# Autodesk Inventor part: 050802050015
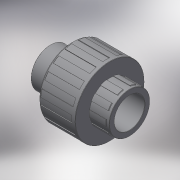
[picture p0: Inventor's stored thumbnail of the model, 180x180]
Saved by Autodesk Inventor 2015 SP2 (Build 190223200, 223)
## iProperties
Created: 2017-10
Part Number: 050802050015
Material: Generic
Description: PLASSON UNION+O RING THR-CEM 50-1.1/2"
Document SubType Name: Modeling
Designer: KIM
Density: 1 g/cm^3
Appearance: Default
Author: KIM
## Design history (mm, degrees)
derived "050802.ipt"
feature "Solid1::050802.ipt"
tag "TaggingFeature1"
body "Solid1"
other parameters: "d0" = 72, "d4" = 44.845, "d6" = 62.5, "d7" = 64, "d8" = 79, "d9" = 31, "d10" = 24, "d11" = 42.5, "d12" = 47.5, "d14" = 18, "d15" = 23.25, "d16" = 15.3, "d17" = 2.4, "d19" = 77.42, "d20" = 3.1, "d21" = 2.37, "d25" = 7.9, "d26" = 3.95, "d27" = 24.885, "d28" = 0, "d32" = 7.9, "d33" = 3.95, "d35" = 0, "d39" = 0.5, "d45" = 0.75, "d49" = 360 deg, "d51" = 0.79, "d55" = 360 deg, "E_" = 79, "H_" = 39, "l_" = 31, "lt_" = 24, "Z_" = 11, "G_" = 44.845, "d13" = 17, "d24" = 27.65, "d40" = 0.75, "d44" = 0.79
